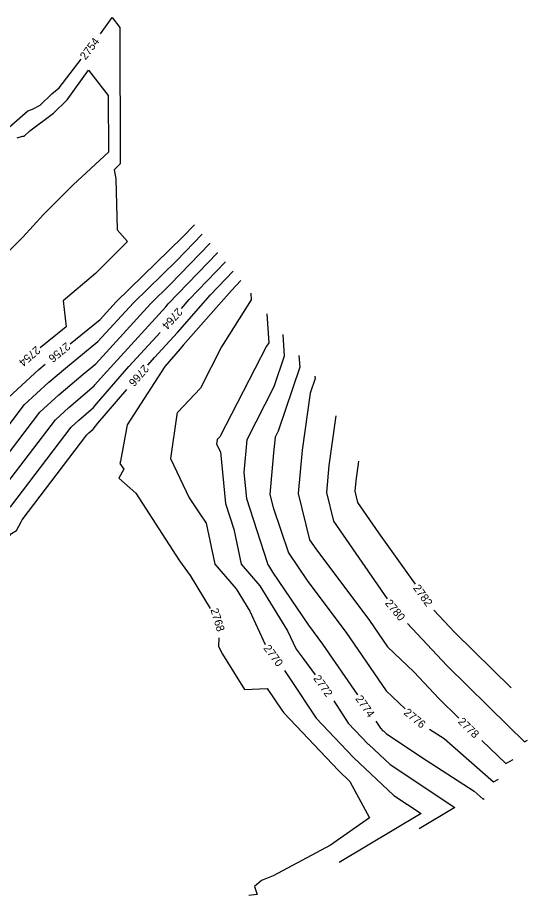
# Model space of a CAD drawing. Extents: x 1326424 to 1329294, y 1001359 to 1003823.
# Drawn here: x 1328982.9 to 1329110.3, y 1001528.8 to 1001748.2 of the extents above; entities that cross this region are included whole.
import ezdxf

# ---------------------------------------------------------------- set-up
doc = ezdxf.new("R2010")
doc.units = 0
doc.layers.add('Prop Rem of Exist Asph Pvmt', color=7, linetype='Continuous')
doc.layers.add('Scratch_Level_3', color=7, linetype='Continuous')

msp = doc.modelspace()

# ---------------------------------------------------------------- linework, layer by layer
at = {"layer": 'Prop Rem of Exist Asph Pvmt'}
for points in [[(1328959.99, 1001619.23), (1328966.19, 1001628.23), (1328969.67, 1001632.3), (1328970.4, 1001632.86), (1328979.33, 1001637.46), (1328988.51, 1001649.55), (1328993.26, 1001653.89), (1328999.28, 1001659.07), (1329002.47, 1001661.66), (1329016.14, 1001676.65), (1329021.05, 1001681.45), (1329030.95, 1001691.75), (1329030.96, 1001691.77)], [(1329062.45, 1001648.69), (1329060.69, 1001636.23), (1329060.08, 1001629.52), (1329061.87, 1001622.33), (1329075.23, 1001602.93), (1329075.26, 1001602.89)], [(1329080.35, 1001596.74), (1329090.17, 1001586.23), (1329105.52, 1001571.14), (1329109.57, 1001567.22), (1329110.27, 1001567.61)]]:
    msp.add_lwpolyline(points, dxfattribs=at)
at = {"layer": 'Scratch_Level_3'}
for points in [[(1329003.65, 1001744.14), (1329006.54, 1001748.19), (1329008.46, 1001745.74), (1329008.57, 1001711.66), (1329008.4, 1001711.5), (1329007.07, 1001710.16), (1329007.45, 1001707.87), (1329007.84, 1001695.12), (1329010.4, 1001692.24), (1329002.39, 1001684.23), (1328994.3, 1001677.38), (1328995.07, 1001670.94), (1328988.58, 1001665.66)], [(1328951.39, 1001743.73), (1328949.38, 1001737.68), (1328952.05, 1001726.66), (1328953.09, 1001725.12), (1328951.39, 1001707.48), (1328951.56, 1001707.37), (1328959.66, 1001702.47), (1328965.4, 1001707.25), (1328968.1, 1001709.72), (1328985.51, 1001724.92), (1328986.68, 1001725.31), (1328988.59, 1001726.32), (1328991.46, 1001729.11), (1328993.28, 1001730.65), (1328998.82, 1001737.77)], [(1328982.85, 1001718.15), (1328984.17, 1001718.58), (1328984.54, 1001718.52), (1328986.01, 1001719.87), (1328991.9, 1001724.3), (1328995.33, 1001727.64), (1329000.64, 1001735.08), (1329005.58, 1001728.72), (1329005.63, 1001714.57), (1328996.78, 1001706.41), (1328989.4, 1001698.99), (1328984.26, 1001693.3), (1328971.13, 1001680.24), (1328968.21, 1001677.43)], [(1328996.05, 1001666.64), (1329003.55, 1001672.75), (1329007.58, 1001677.17), (1329024.19, 1001693.39), (1329027.08, 1001696.4), (1329027.11, 1001696.43)], [(1328965.15, 1001635.95), (1328965.44, 1001636.3), (1328966.42, 1001637.06), (1328978.37, 1001643.2), (1328984.61, 1001651.42), (1328990.77, 1001657.05), (1328994.89, 1001660.6), (1329003.01, 1001667.21), (1329011.86, 1001676.91), (1329022.62, 1001687.42), (1329029.01, 1001694.08), (1329029.04, 1001694.1)], [(1328960.88, 1001611.96), (1328964.14, 1001615.52), (1328968.97, 1001622.54), (1328973.89, 1001628.29), (1328974.37, 1001628.67), (1328980.28, 1001631.71), (1328992.4, 1001647.67), (1328995.76, 1001650.74), (1329002.07, 1001656.16), (1329002.25, 1001656.39), (1329004.37, 1001658.85), (1329019.97, 1001675.92), (1329020.57, 1001676.62), (1329032.88, 1001689.43), (1329032.89, 1001689.44)], [(1329023.84, 1001675.48), (1329025.82, 1001677.75), (1329034.81, 1001687.1), (1329034.82, 1001687.11)], [(1329015.47, 1001661.28), (1329017.13, 1001663.2), (1329022.88, 1001669.49), (1329031.08, 1001678.88), (1329036.74, 1001684.78), (1329036.75, 1001684.78)], [(1329038.67, 1001682.46), (1329038.67, 1001682.45), (1329036.33, 1001680.01), (1329024.33, 1001666.28), (1329023.5, 1001665.37), (1329019.72, 1001661), (1329010.29, 1001646.4), (1329008.68, 1001637.29), (1329008.51, 1001636.75), (1329009.47, 1001635.33), (1329008.24, 1001633.11), (1329012.47, 1001629.36), (1329019.89, 1001617.83), (1329023.35, 1001612.46), (1329026.02, 1001608.75), (1329031, 1001600.54)], [(1329041.21, 1001679.29), (1329041.31, 1001677.66), (1329033.89, 1001665.88), (1329028.59, 1001655.61), (1329022.91, 1001649.45), (1329022.7, 1001649.14), (1329022.68, 1001648.98), (1329022.69, 1001648.95), (1329021.14, 1001637.98), (1329025.83, 1001628.19), (1329028.48, 1001624.2), (1329030.02, 1001621.86), (1329032.18, 1001611.61), (1329037.53, 1001605.41), (1329040.94, 1001599.8), (1329044.79, 1001591.47)], [(1329045.21, 1001674.12), (1329045.66, 1001666.93), (1329045.1, 1001666.05), (1329033.41, 1001643.43), (1329032.81, 1001642.78), (1329032.64, 1001641.61), (1329033.59, 1001639.63), (1329034.86, 1001626.71), (1329036.93, 1001620.33), (1329038.77, 1001611.58), (1329043.45, 1001606.16), (1329050.36, 1001594.96), (1329052.5, 1001590.34), (1329054.27, 1001588), (1329057.24, 1001583.91)], [(1328949.41, 1001598.96), (1328962.11, 1001605.55), (1328963.4, 1001606.71), (1328968.98, 1001612.83), (1328971.75, 1001616.86), (1328978.11, 1001624.29), (1328978.35, 1001624.48), (1328981.24, 1001625.97), (1328996.3, 1001645.8), (1328998.25, 1001647.58), (1329001.93, 1001650.74), (1329002.61, 1001651.62), (1329010.75, 1001661.02), (1329018.51, 1001669.52)], [(1329049.21, 1001668.95), (1329049.55, 1001663.53), (1329046.96, 1001655.88), (1329040.2, 1001642.62), (1329039.44, 1001634.5), (1329040.07, 1001628.02), (1329045.26, 1001612.03), (1329045.36, 1001611.55), (1329045.62, 1001611.25), (1329046.64, 1001609.59), (1329055.61, 1001596.3), (1329059.12, 1001591.61), (1329067.82, 1001578.89)], [(1329053.21, 1001663.77), (1329053.4, 1001660.78), (1329047.99, 1001644.79), (1329047.23, 1001643.3), (1329046.87, 1001639.43), (1329045.92, 1001628.97), (1329046.73, 1001625.71), (1329050.62, 1001614.45), (1329055.45, 1001607.29), (1329064.98, 1001594.55), (1329074.99, 1001579.92), (1329079.72, 1001575.44)], [(1328926.54, 1001641.67), (1328926.35, 1001640.7), (1328926.16, 1001639.45), (1328926.41, 1001638.8), (1328928.27, 1001631.88), (1328929.08, 1001629.75), (1328931.25, 1001624.02), (1328931.43, 1001621.77), (1328936.81, 1001620.16), (1328938.09, 1001617.43), (1328940.91, 1001616.75), (1328944.07, 1001618.39), (1328948.49, 1001622.37), (1328949.61, 1001623.6), (1328960.62, 1001639.6), (1328961.22, 1001640.3), (1328962.44, 1001641.25), (1328977.42, 1001648.95), (1328980.72, 1001653.3), (1328988.28, 1001660.21), (1328989.86, 1001661.57)], [(1329057.21, 1001658.6), (1329057.25, 1001658.02), (1329056.01, 1001654.35), (1329053.98, 1001640.05), (1329053, 1001629.25), (1329055.87, 1001617.68), (1329057.41, 1001615.45), (1329070.84, 1001597.49), (1329075.34, 1001590.92), (1329081.89, 1001584.71), (1329088.22, 1001577.92), (1329093.17, 1001573.07)], [(1328937.96, 1001595.78), (1328948.87, 1001593.14), (1328966.62, 1001602.34), (1328967.12, 1001602.8), (1328973.82, 1001610.13), (1328974.53, 1001611.17), (1328981.42, 1001619.23), (1328982.67, 1001620), (1328983.87, 1001622.16), (1328984.08, 1001622.7), (1329000.2, 1001643.92), (1329000.74, 1001644.43), (1329001.78, 1001645.31), (1329002.97, 1001646.84), (1329010.24, 1001655.23)], [(1329068.09, 1001637.29), (1329067.4, 1001632.42), (1329067.16, 1001629.79), (1329067.86, 1001626.98), (1329073.09, 1001619.39), (1329082.23, 1001606.57)], [(1329086.92, 1001600.09), (1329092.11, 1001594.53), (1329106.24, 1001580.65)], [(1329033.23, 1001593.21), (1329033.14, 1001590.99), (1329034.12, 1001589.09), (1329039.58, 1001580.23), (1329045.23, 1001580.55), (1329048.97, 1001575.08), (1329049.4, 1001574.43), (1329063.05, 1001560.02), (1329063.05, 1001560.01), (1329065.94, 1001557.3), (1329070.85, 1001548.19), (1329061.08, 1001541.37), (1329046.79, 1001533.71), (1329043.84, 1001532.49), (1329042.11, 1001531.07), (1329042.75, 1001529.06), (1329040.73, 1001528.79)], [(1329049.56, 1001585.05), (1329051.13, 1001582.75), (1329057.47, 1001573.14), (1329066.76, 1001563.33), (1329066.84, 1001563.28), (1329076.92, 1001553.79), (1329083.76, 1001549.24), (1329063.26, 1001537.06)], [(1329061.88, 1001577.4), (1329065.53, 1001571.86), (1329070.47, 1001566.64), (1329070.62, 1001566.55), (1329075.97, 1001561.51), (1329092.15, 1001550.75), (1329083.22, 1001545.44)], [(1329072.38, 1001572.33), (1329073.06, 1001571.39), (1329073.6, 1001570.57), (1329074.19, 1001569.96), (1329074.4, 1001569.81), (1329075.02, 1001569.23), (1329083.6, 1001563.52), (1329096.95, 1001554.89), (1329099.23, 1001552.89), (1329099.46, 1001553.02)], [(1329085.84, 1001570.34), (1329089.49, 1001567.98), (1329101.83, 1001557.2), (1329103.06, 1001557.88)], [(1329098.91, 1001567.5), (1329104.85, 1001561.74), (1329106.67, 1001562.74)]]:
    msp.add_lwpolyline(points, dxfattribs=at)

# ---------------------------------------------------------------- texts
at = {"layer": 'Prop Rem of Exist Asph Pvmt'}
msp.add_text('2780', height=2, rotation=309.6481, dxfattribs=at).set_placement((1329074.57, 1001601.78))
at = {"layer": 'Scratch_Level_3'}
for s, rotation, p in [('2754', 52.8556, (1328999.91, 1001737.46)), ('2764', 228.1816, (1329022.84, 1001675.8)), ('2754', 221.0367, (1328987.55, 1001666.21)), ('2756', 219.3284, (1328995.08, 1001667.16)), ('2766', 229.1324, (1329014.43, 1001661.61)), ('2782', 305.9261, (1329081.63, 1001605.62)), ('2768', 286.9229, (1329031.08, 1001600.24)), ('2770', 306.5626, (1329044.26, 1001590.55)), ('2772', 305.4774, (1329056.69, 1001583.01)), ('2774', 304.8111, (1329067.21, 1001577.96)), ('2776', 320.2506, (1329079.22, 1001574.21)), ('2778', 315.847, (1329092.76, 1001572.06))]:
    msp.add_text(s, height=2, rotation=rotation, dxfattribs=at).set_placement(p)

doc.saveas('drawing.dxf')
